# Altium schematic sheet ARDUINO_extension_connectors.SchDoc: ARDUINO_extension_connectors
size A3; Date: Not used; ApprovedBy: Not used; CheckedBy: Not used; Author: Not used; CompanyName: STMicroelectronics; DrawnBy: Not used; Engineer: Not used; Organization: Not used; Address1: Not used; Address2: Not used; Address3: Not used; Address4: Not used; DocumentNumber: 5; Revision: Not used; SheetNumber: 5; SheetTotal: 9
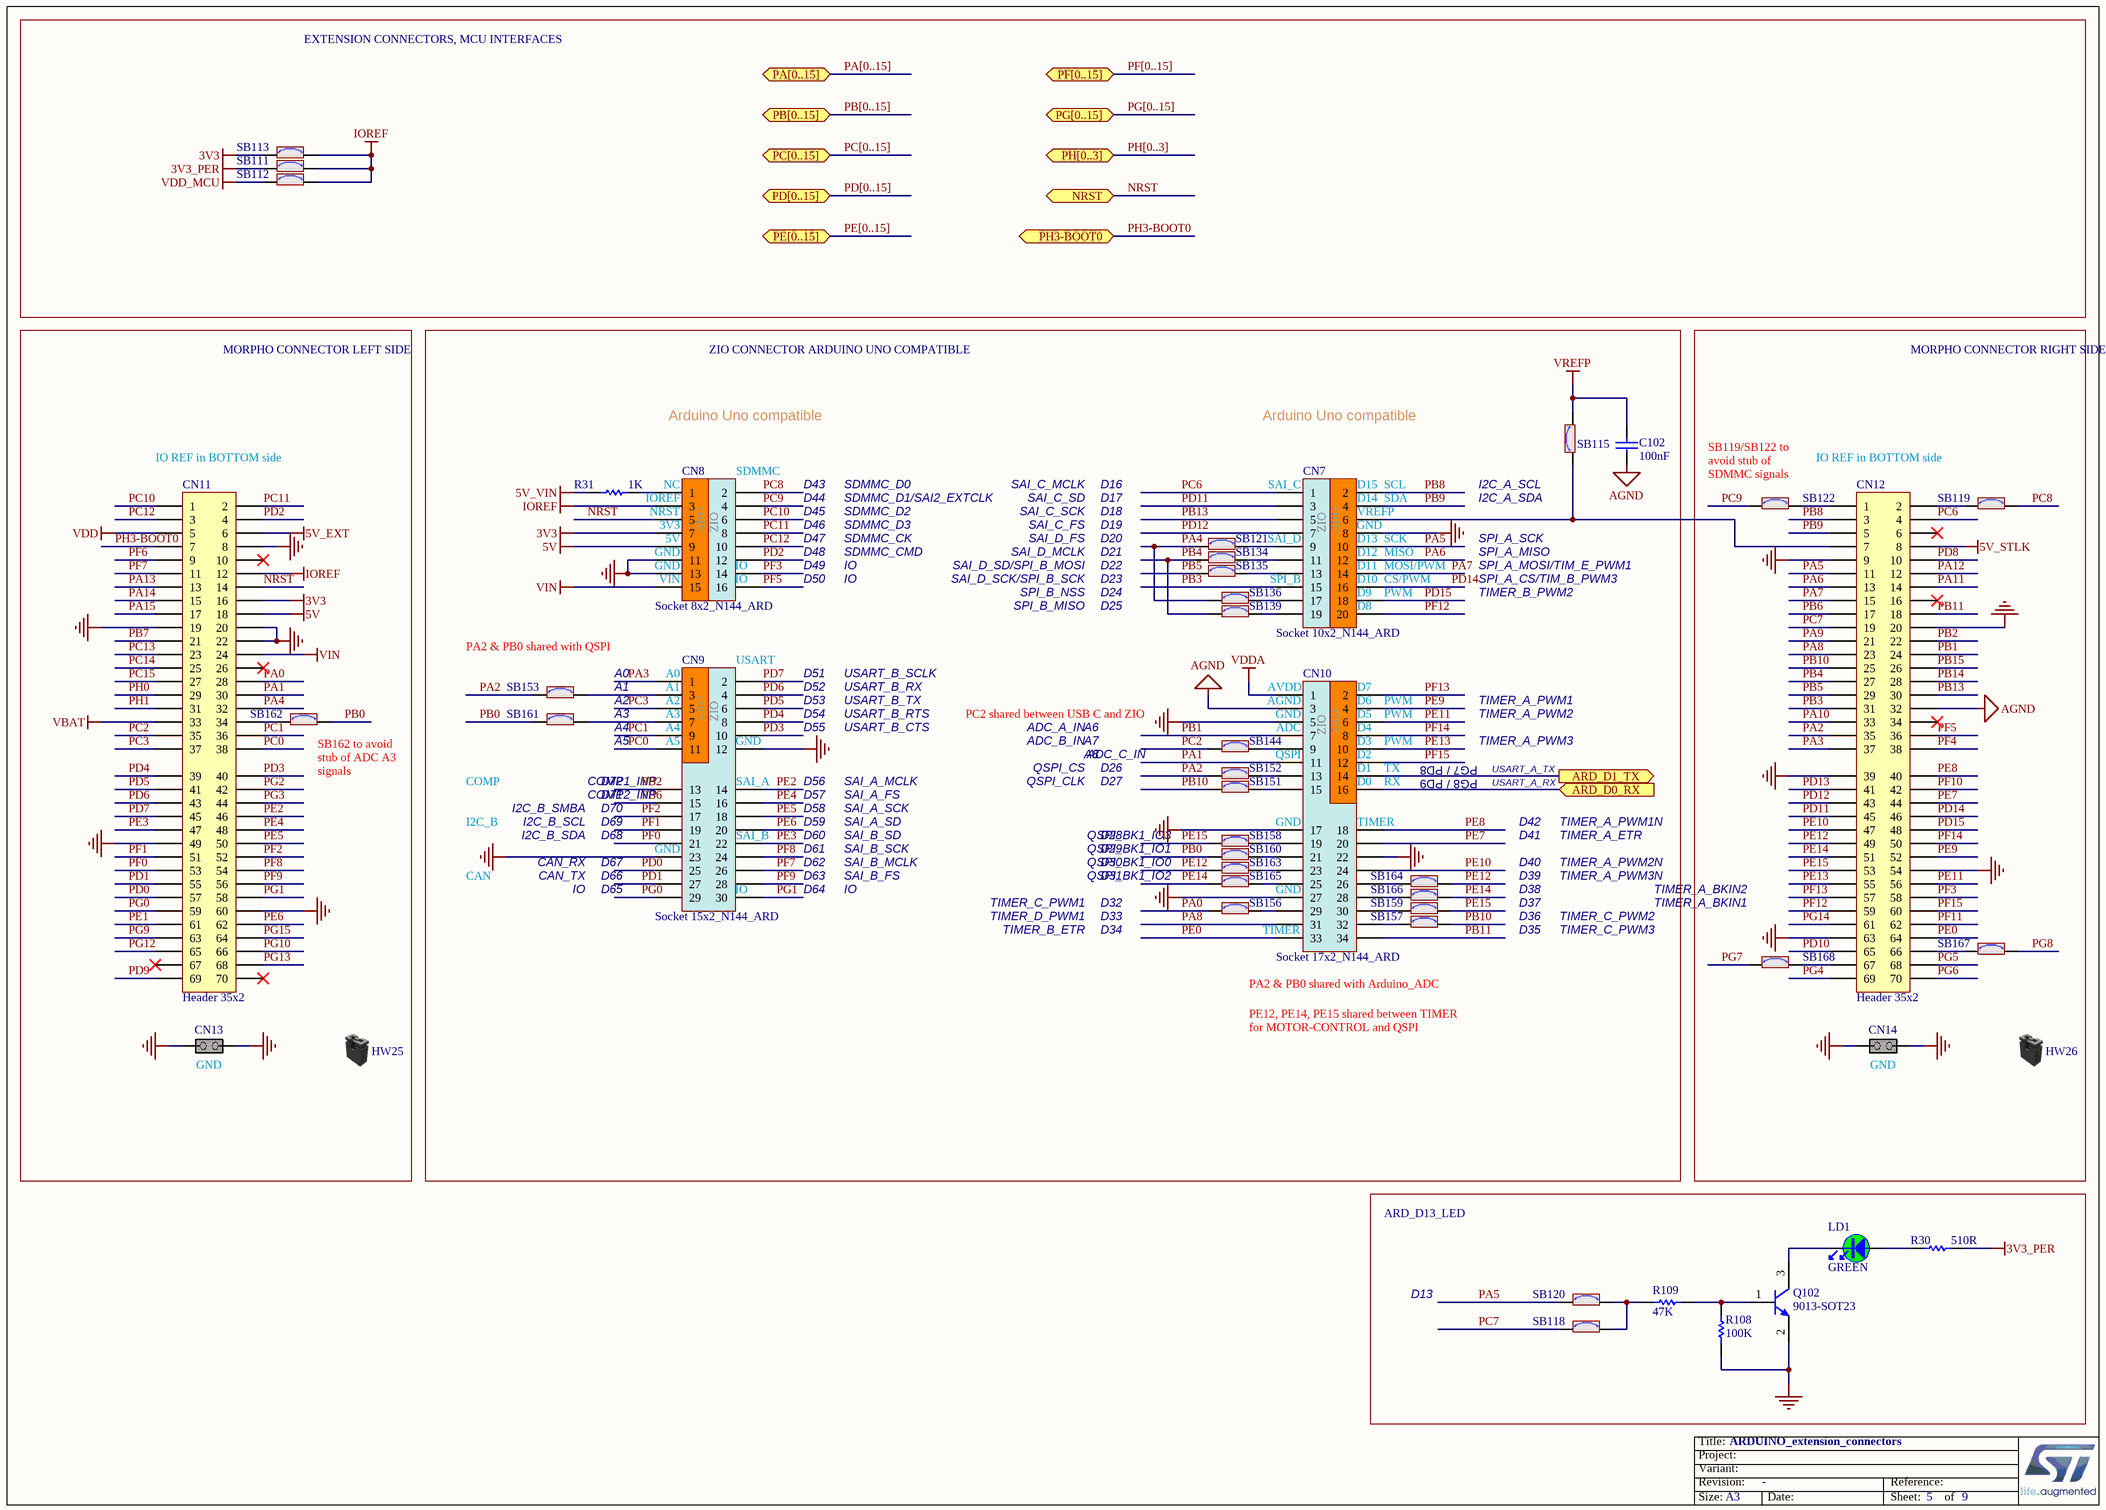
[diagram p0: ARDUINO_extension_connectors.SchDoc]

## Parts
C102  value 100nF  [C0603]
CN7  value Socket 10x2_N144_ARD  [CON_SAMTEC_SSW-110-23-X-D_N144_ARD]
CN8  value Socket 8x2_N144_ARD  [CON_SAMTEC_SSW-108-23-X-D_N144_ARD]
CN9  value Socket 15x2_N144_ARD  [CON_SAMTEC_SSW-115-23-X-D_N144_ARD]
CN10  value Socket 17x2_N144_ARD  [CON_SAMTEC_SSW-117-23-X-D_N144_ARD]
CN11  value Header 35x2  [CON_SAMTEC_TSW-135-07-X-D]
CN12  value Header 35x2  [CON_SAMTEC_TSW-135-07-X-D]
CN13  (no value)  [CON_SAMTEC_TSW-102-09-X-S]
CN14  (no value)  [CON_SAMTEC_TSW-102-09-X-S]
HW25  (no value)  (mechanical)
HW26  (no value)  (mechanical)
LD1  value GREEN  [LED_0603_GREEN]
Q102  value 9013-SOT23  [NPN_SOT23]
R30  value 510R  [R0603]
R31  value 1K  [R0603]
R108  value 100K  [R0603]
R109  value 47K  [R0603]
SB111  (no value)  [SOLDER-BRIDGE_R0603-0R]
SB112  (no value)  [SOLDER-BRIDGE_R0603-0R]
SB113  (no value)  [SOLDER-BRIDGE_R0603-0R]
SB115  (no value)  [SOLDER-BRIDGE_R0603-0R]
SB118  (no value)  [SOLDER-BRIDGE_R0603-0R]
SB119  (no value)  [SOLDER-BRIDGE_R0603-0R]
SB120  (no value)  [SOLDER-BRIDGE_R0603-0R]
SB121  (no value)  [SOLDER-BRIDGE_R0603-0R]
SB122  (no value)  [SOLDER-BRIDGE_R0603-0R]
SB134  (no value)  [SOLDER-BRIDGE_R0603-0R]
SB135  (no value)  [SOLDER-BRIDGE_R0603-0R]
SB136  (no value)  [SOLDER-BRIDGE_R0603-0R]
SB139  (no value)  [SOLDER-BRIDGE_R0603-0R]
SB144  (no value)  [SOLDER-BRIDGE_R0603-0R]
SB151  (no value)  [SOLDER-BRIDGE_R0603-0R]
SB152  (no value)  [SOLDER-BRIDGE_R0603-0R]
SB153  (no value)  [SOLDER-BRIDGE_R0603-0R]
SB156  (no value)  [SOLDER-BRIDGE_R0603-0R]
SB157  (no value)  [SOLDER-BRIDGE_R0603-0R]
SB158  (no value)  [SOLDER-BRIDGE_R0603-0R]
SB159  (no value)  [SOLDER-BRIDGE_R0603-0R]
SB160  (no value)  [SOLDER-BRIDGE_R0603-0R]
SB161  (no value)  [SOLDER-BRIDGE_R0603-0R]
SB162  (no value)  [SOLDER-BRIDGE_R0603-0R]
SB163  (no value)  [SOLDER-BRIDGE_R0603-0R]
SB164  (no value)  [SOLDER-BRIDGE_R0603-0R]
SB165  (no value)  [SOLDER-BRIDGE_R0603-0R]
SB166  (no value)  [SOLDER-BRIDGE_R0603-0R]
SB167  (no value)  [SOLDER-BRIDGE_R0603-0R]
SB168  (no value)  [SOLDER-BRIDGE_R0603-0R]

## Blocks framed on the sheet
EXTENSION CONNECTORS, MCU INTERFACES: SB111-SB113

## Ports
ARD_D0_RX (in), ARD_D1_TX (out), NRST, PA[0..15] (bidir), PB[0..15] (bidir), PC[0..15] (bidir), PD[0..15] (bidir), PE[0..15] (bidir), PF[0..15] (bidir), PG[0..15] (bidir), PH3-BOOT0, PH[0..3] (bidir)

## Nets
3V3: CN8.7 CN11.16 SB113.1
3V3_PER: R30.2 SB111.1
5V: CN8.9 CN11.18
5V_EXT: CN11.6
5V_STLK: CN12.8
5V_VIN: R31.2
AGND: C102.1 CN10.3 CN12.32
GND: CN7.8 CN8.11 CN8.13 CN9.12 CN9.23 CN10.5 CN10.17 CN10.22 CN10.27 CN11.8 CN11.19 CN11.20 CN11.22 CN11.49 CN11.60 CN12.9 CN12.20 CN12.39 CN12.54 CN12.63 CN13.1(COMMON) CN13.2(NO) CN14.1(COMMON) CN14.2(NO) Q102.2(E) R108.1
IOREF: CN8.3 CN11.12 SB111.2 SB112.2 SB113.2
VBAT: CN11.33
VDD: CN11.5
VDD_MCU: SB112.1
VDDA: CN10.1
VIN: CN8.15 CN11.24
VREFP: C102.2 SB115.2
ARD_D0_RX: CN10.16 ; port ARD_D0_RX
ARD_D1_TX: CN10.14 ; port ARD_D1_TX
NRST: CN8.5 CN11.14 ; port NRST
PA0: CN11.28 SB156.1
PA1: CN10.11 CN11.30
PA2: CN12.35 SB152.1 SB153.1
PA3: CN9.1 CN12.37
PA4: CN11.32 SB121.1 SB136.1
PA5: CN7.10 CN12.11 SB120.1
PA6: CN7.12 CN12.13
PA7: CN7.14 CN12.15
PA8: CN10.31 CN12.23
PA9: CN12.21
PA10: CN12.33
PA11: CN12.14
PA12: CN12.12
PA13: CN11.13
PA14: CN11.15
PA15: CN11.17
PB0: SB160.1 SB161.1 SB162.2
PB1: CN10.7 CN12.24
PB2: CN9.13 CN12.22
PB3: CN7.15 CN12.31
PB4: CN12.27 SB134.1 SB139.1
PB5: CN12.29 SB135.1
PB6: CN9.15 CN12.17
PB7: CN11.21
PB8: CN7.2 CN12.3
PB9: CN7.4 CN12.5
PB10: CN12.25 SB151.1 SB157.2
PB11: CN10.34 CN12.18
PB13: CN7.5 CN12.30
PB14: CN12.28
PB15: CN12.26
PC0: CN9.11 CN11.38
PC1: CN9.9 CN11.36
PC2: CN11.35 SB144.1
PC3: CN9.5 CN11.37
PC6: CN7.1 CN12.4
PC7: CN12.19 SB118.1
PC8: CN8.2 SB119.2
PC9: CN8.4 SB122.1
PC10: CN8.6 CN11.1
PC11: CN8.8 CN11.2
PC12: CN8.10 CN11.3
PC13: CN11.23
PC14: CN11.25
PC15: CN11.27
PD0: CN9.25 CN11.57
PD1: CN9.27 CN11.55
PD2: CN8.12 CN11.4
PD3: CN9.10 CN11.40
PD4: CN9.8 CN11.39
PD5: CN9.6 CN11.41
PD6: CN9.4 CN11.43
PD7: CN9.2 CN11.45
PD8: CN12.10
PD9: CN11.69
PD10: CN12.65
PD11: CN7.3 CN12.45
PD12: CN7.7 CN12.43
PD13: CN12.41
PD14: CN7.16 CN12.46
PD15: CN7.18 CN12.48
PE0: CN10.33 CN12.64
PE1: CN11.61
PE2: CN9.14 CN11.46
PE3: CN9.22 CN11.47
PE4: CN9.16 CN11.48
PE5: CN9.18 CN11.50
PE6: CN9.20 CN11.62
PE7: CN10.20 CN12.44
PE8: CN10.18 CN12.40
PE9: CN10.4 CN12.52
PE10: CN10.24 CN12.47
PE11: CN10.6 CN12.56
PE12: CN12.49 SB163.1 SB164.2
PE13: CN10.10 CN12.55
PE14: CN12.51 SB165.1 SB166.2
PE15: CN12.53 SB158.1 SB159.2
PF0: CN9.21 CN11.53
PF1: CN9.19 CN11.51
PF2: CN9.17 CN11.52
PF3: CN8.14 CN12.58
PF4: CN12.38
PF5: CN8.16 CN12.36
PF6: CN11.9
PF7: CN9.26 CN11.11
PF8: CN9.24 CN11.54
PF9: CN9.28 CN11.56
PF10: CN12.42
PF11: CN12.62
PF12: CN7.20 CN12.59
PF13: CN10.2 CN12.57
PF14: CN10.8 CN12.50
PF15: CN10.12 CN12.60
PG0: CN9.29 CN11.59
PG1: CN9.30 CN11.58
PG2: CN11.42
PG3: CN11.44
PG4: CN12.69
PG5: CN12.68
PG6: CN12.70
PG7: SB168.1
PG8: SB167.2
PG9: CN11.63
PG10: CN11.66
PG12: CN11.65
PG13: CN11.68
PG14: CN12.61
PG15: CN11.64
PH0: CN11.29
PH1: CN11.31
PH3-BOOT0: CN11.7 ; port PH3-BOOT0
NetCN7_6: CN7.6 CN12.7 SB115.1
NetCN7_9: CN7.9 SB121.2
NetCN7_11: CN7.11 SB134.2
NetCN7_13: CN7.13 SB135.2
NetCN7_17: CN7.17 SB136.2
NetCN7_19: CN7.19 SB139.2
NetCN8_1: CN8.1 R31.1
NetCN9_3: CN9.3 SB153.2
NetCN9_7: CN9.7 SB161.2
NetCN10_9: CN10.9 SB144.2
NetCN10_13: CN10.13 SB152.2
NetCN10_15: CN10.15 SB151.2
NetCN10_19: CN10.19 SB158.2
NetCN10_21: CN10.21 SB160.2
NetCN10_23: CN10.23 SB163.2
NetCN10_25: CN10.25 SB165.2
NetCN10_26: CN10.26 SB164.1
NetCN10_28: CN10.28 SB166.1
NetCN10_29: CN10.29 SB156.2
NetCN10_30: CN10.30 SB159.1
NetCN10_32: CN10.32 SB157.1
NetCN11_34: CN11.34 SB162.1
NetCN12_1: CN12.1 SB122.2
NetCN12_2: CN12.2 SB119.1
NetCN12_66: CN12.66 SB167.1
NetCN12_67: CN12.67 SB168.2
NetLD1_1: LD1.1 R30.1
NetLD1_2: LD1.2 Q102.3(C)
NetQ102_1: Q102.1(B) R108.2 R109.2
NetR109_1: R109.1 SB118.2 SB120.2

Not connected (* = marked no-connect by the designer): CN11 10* 26* 67* 70*; CN12 6* 16* 34*

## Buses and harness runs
bus PA[0..15] = port PA[0..15]
bus PB[0..15] = port PB[0..15]
bus PC[0..15] = port PC[0..15]
bus PD[0..15] = port PD[0..15]
bus PE[0..15] = port PE[0..15]
bus PF[0..15] = port PF[0..15]
bus PG[0..15] = port PG[0..15]
bus PH[0..3] = port PH[0..3]

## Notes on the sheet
- MORPHO CONNECTOR LEFT SIDE
- ZIO CONNECTOR ARDUINO UNO COMPATIBLE
- MORPHO CONNECTOR RIGHT SIDE
- Arduino Uno compatible
- (near CN11) IO REF in BOTTOM side
- (near CN8) NC
- (near CN8) IOREF
- (near CN8) NRST
- (near CN8) SDMMC
- D43
- D44
- D45
- SDMMC_D0
- SDMMC_D1/SAI2_EXTCLK
- SDMMC_D2
- SAI_C_SD
- SAI_C_SCK
- SAI_C_MCLK
- D16
- D17
- D18
- (near CN7) SAI_C
- (near CN7) VREFP
- (near CN7) D14
- (near CN7) D15
- (near CN7) SCL
- (near CN7) SDA
- (near SB115) I2C_A_SCL
- I2C_A_SDA
- (near SB122) SB119/SB122 to avoid stub of SDMMC signals
- IO REF in BOTTOM side
- (near CN8) 3V3
- (near CN8) 5V
- (near CN8) GND
- (near CN8) VIN
- (near CN8) IO
- D46
- D47
- D48
- D49
- D50
- SDMMC_CK
- SDMMC_CMD
- SDMMC_D3
- IO
- SAI_C_FS
- SAI_D_SD/SPI_B_MOSI
- SAI_D_SCK/SPI_B_SCK
- SAI_D_FS
- SAI_D_MCLK
- D19
- D20
- D21
- D22
- D23
- (near CN7) SPI_B
- (near CN7) SAI_D
- (near CN7) D10
- (near CN7) D11
- (near CN7) D12
- (near CN7) D13
- (near CN7) SCK
- (near CN7) GND
- (near CN7) MISO
- (near CN7) MOSI/PWM
- (near CN7) CS/PWM
- SPI_A_CS/TIM_B_PWM3
- SPI_A_MOSI/TIM_E_PWM1
- SPI_A_SCK
- SPI_A_MISO
- PA2 & PB0 shared with QSPI
- SPI_B_MISO
- SPI_B_NSS
- D24
- D25
- (near CN7) D8
- (near CN7) D9
- (near CN7) PWM
- TIMER_B_PWM2
- A0
- A1
- A2
- A3
- (near CN9) A0
- (near CN9) A1
- (near CN9) A2
- (near CN9) A3
- (near CN9) USART
- D51
- D52
- D53
- D54
- USART_B_TX
- USART_B_RX
- USART_B_SCLK
- USART_B_RTS
- PC2 shared between USB C and ZIO
- (near CN10) GND
- (near CN10) AVDD
- (near CN10) AGND
- (near CN10) D7
- (near CN10) D6
- (near CN10) D5
- (near CN10) PWM
- TIMER_A_PWM1
- TIMER_A_PWM2
- (near SB162) SB162 to avoid stub of ADC A3 signals
- COMP
- COMP1_INP
- D72
- A4
- A5
- (near CN9) A4
- (near CN9) A5
- (near CN9) SAI_A
- (near CN9) GND
- D55
- D56
- SAI_A_MCLK
- USART_B_CTS
- QSPI_CLK
- QSPI_CS
- ADC_A_IN
- ADC_B_IN
- ADC_C_IN
- A6
- A7
- A8
- D26
- D27
- (near CN10) ADC
- (near CN10) QSPI
- (near CN10) D2
- (near CN10) D4
- (near CN10) D3
- (near CN10) D1
- (near CN10) D0
- (near CN10) TX
- (near CN10) RX
- TIMER_A_PWM3
- PG8 / PD9
- PG7 / PD8
- USART_A_TX
- USART_A_RX
- I2C_B
- I2C_B_SCL
- I2C_B_SDA
- I2C_B_SMBA
- COMP2_INP
- D71
- D70
- D69
- D68
- (near CN9) SAI_B
- D57
- D58
- D59
- D60
- D61
- SAI_A_SD
- SAI_A_SCK
- SAI_A_FS
- SAI_B_SD
- SAI_B_SCK
- QSPI_BK1_IO1
- QSPI_BK1_IO3
- D28
- D29
- (near CN10) TIMER
- D41
- D42
- TIMER_A_PWM1N
- TIMER_A_ETR
- CAN
- CAN_TX
- CAN_RX
- D67
- D66
- D65
- (near CN9) IO
- D62
- D63
- D64
- SAI_B_FS
- SAI_B_MCLK
- TIMER_D_PWM1
- TIMER_C_PWM1
- QSPI_BK1_IO0
- QSPI_BK1_IO2
- D30
- D31
- D32
- D33
- D36
- D37
- D38
- D39
- D40
- TIMER_A_PWM2N
- TIMER_A_PWM3N
- TIMER_C_PWM2
- TIMER_A_BKIN1
- TIMER_A_BKIN2
- TIMER_B_ETR
- D34
- PA2 & PB0 shared with Arduino_ADC
- TIMER
- D35
- TIMER_C_PWM3
- PE12, PE14, PE15 shared between TIMER for MOTOR-CONTROL and QSPI
- (near CN13) GND
- (near CN14) GND
- ARD_D13_LED
- D13

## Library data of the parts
C102 = MCD-00211: Capacitor, MLCC, 100nF, 16V, X7R, 10%, 0603, T=0,8mm; Manufacturer_Part_Number: CC0603KRX7R7BB104; Manufacturer: YAGEO; Provided_By: Subcon; Initial_Board_Reference: MB1319
CN7 = MCD-01039: Socket, 10x2, 2.54mm, VR, TH, Height 8.51mm/10mm, Low insertion force.; Part_Type: Connector; Manufacturer_Part_Number: SSW-110-23-x-D; Manufacturer: SAMTEC; Provided_By: Subcon; Initial_Board_Reference: MB1361; Remark: Socket dedicated to Arduino+ZIO connector on NUCLEO144
CN8 = MCD-01037: Socket, 8x2, 2.54mm, VR, TH, Height 8.51mm/10mm, Low insertion force.; Part_Type: Connector; Manufacturer_Part_Number: SSW-108-23-x-D; Manufacturer: SAMTEC; Provided_By: Subcon; Initial_Board_Reference: MB1361; Remark: Socket dedicated to Arduino+ZIO connector on NUCLEO144
CN9 = MCD-01040: Socket, 15x2, 2.54mm, VR, TH, Height 8.51mm/10mm, Low insertion force.; Part_Type: Connector; Manufacturer_Part_Number: SSW-115-23-x-D; Manufacturer: SAMTEC; Provided_By: Subcon; Initial_Board_Reference: MB1361; Remark: Socket dedicated to Arduino+ZIO connector on NUCLEO144
CN10 = MCD-01041: Socket, 17x2, 2.54mm, VR, TH, Height 8.51mm/10mm, Low insertion force; Part_Type: Connector; Manufacturer_Part_Number: SSW-117-23-x-D; Manufacturer: SAMTEC; Provided_By: Subcon; Initial_Board_Reference: MB1361; Remark: Socket dedicated to Arduino+ZIO connector on NUCLEO144
CN11 CN12 = MCD-01210: Header, 35x2, 2,54mm, VR, TH, Height 5.84mm/2.54mm; Part_Type: Connector; Manufacturer_Part_Number: TSW-135-07-x-D; Manufacturer: SAMTEC; Provided_By: Subcon; Initial_Board_Reference: MB1361
CN13 CN14 = MCD-00214: Header, 2x1, 2,54mm, VR, TH, Height 5.84mm/10.16mm; Manufacturer_Part_Number: TSW-102-09-x-S; Manufacturer: SAMTEC; Part_Type: Connector; Value: Header 2x1 16mm; Provided_By: Subcon; Initial_Board_Reference: MB1319
HW25 HW26 = MCD-00043: SHUNT 2.54mm BLACK; Manufacturer_Part_Number: SNT-100-BK-G; Manufacturer: SAMTEC; Part_Type: Mechanical; Provided_By: Subcon; Initial_Board_Reference: MB1274
LD1 = MCD-00050: LED, Green, 0603; Part_Type: Display; Manufacturer_Part_Number: 19-213SYGC/S530-E2/TR8; Manufacturer: EVERLIGHT; ECCN_US: EAR99; ECCN_EU: NEC; Provided_By: Subcon; Initial_Board_Reference: MB1274
Q102 = MCD-00073: NPN Bipolar Transistor; Part_Type: IC; Manufacturer_Part_Number: BSR14; Manufacturer: NXP; ECCN_US: EAR99; ECCN_EU: NEC; Provided_By: Subcon; Initial_Board_Reference: MB1274
R30 = MCD-00225: Resistor,510R,0603,1%,1/10W; Manufacturer_Part_Number: RC0603FR-07510RL; Manufacturer: YAGEO; Provided_By: Subcon; Initial_Board_Reference: MB1319
R31 = MCD-00070: Resistor,1K,0603,1%,1/10W; Manufacturer_Part_Number: RC0603FR-071KL; Manufacturer: YAGEO; Provided_By: Subcon; Initial_Board_Reference: MB1274
R108 = MCD-00223: Resistor,100K,0603,1%,1/10W; Manufacturer_Part_Number: RC0603FR-07100KL; Manufacturer: YAGEO; Provided_By: Subcon; Initial_Board_Reference: MB1319
R109 = MCD-00222: Resistor,47K,0603,1%,1/10W; Manufacturer_Part_Number: RC0603FR-0747KL; Manufacturer: YAGEO; Provided_By: Subcon; Initial_Board_Reference: MB1319
SB111-SB113 SB115 SB118-SB122 SB134-SB136 SB139 SB144 SB151-SB153 SB156-SB168 = MCD-00071: Solder Bridge ON; Part_Type: Mechanical; Provided_By: Subcon; Initial_Board_Reference: MB1274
